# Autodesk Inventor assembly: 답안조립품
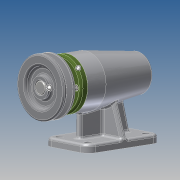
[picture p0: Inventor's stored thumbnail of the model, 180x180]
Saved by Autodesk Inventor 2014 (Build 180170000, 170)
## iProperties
Created: 2018-09
Part Number: 답안조립품
Document SubType Name: Assembly
Designer: kb542
Author: kb542
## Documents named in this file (12)
- C:\Users\kb542\Desktop\480907V1009\답안조립품.iam
- C:\Users\kb542\Desktop\480907V1009\본체.ipt
- C:\Users\kb542\Desktop\480907V1009\V벨트풀리.ipt
- C:\Users\kb542\Desktop\480907V1009\멈춤나사 M3.ipt
- C:\Users\kb542\Desktop\480907V1009\베어링 6004.ipt
- C:\Users\kb542\Desktop\480907V1009\베어링 51202.ipt
- C:\Users\kb542\Desktop\480907V1009\볼트 M4.ipt
- C:\Users\kb542\Desktop\480907V1009\어댑터슬리브.ipt
- C:\Users\kb542\Desktop\480907V1009\오일 실.ipt
- C:\Users\kb542\Desktop\480907V1009\축.ipt
- C:\Users\kb542\Desktop\480907V1009\커버.ipt
- C:\Users\kb542\Desktop\480907V1009\키 5 x 5 x 16.ipt
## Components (1 placed, 1 different names)
1. V벨트풀리:1 — 각도:1, 플러쉬:2
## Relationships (2: Angle 1, Flush 1)
- 각도:1 [Angle]: V벨트풀리:1
- 플러쉬:2 [Flush]: V벨트풀리:1
